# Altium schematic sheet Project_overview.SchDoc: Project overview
size A4; Date: Not used; ApprovedBy: Not used; CheckedBy: Not used; Author: Not used; CompanyName: STMicroelectronics; DrawnBy: Not used; Engineer: Not used; Organization: Not used; Address1: Not used; Address2: Not used; Address3: Not used; Address4: Not used; DocumentNumber: 1; Revision: Not used; SheetNumber: 1; SheetTotal: 9
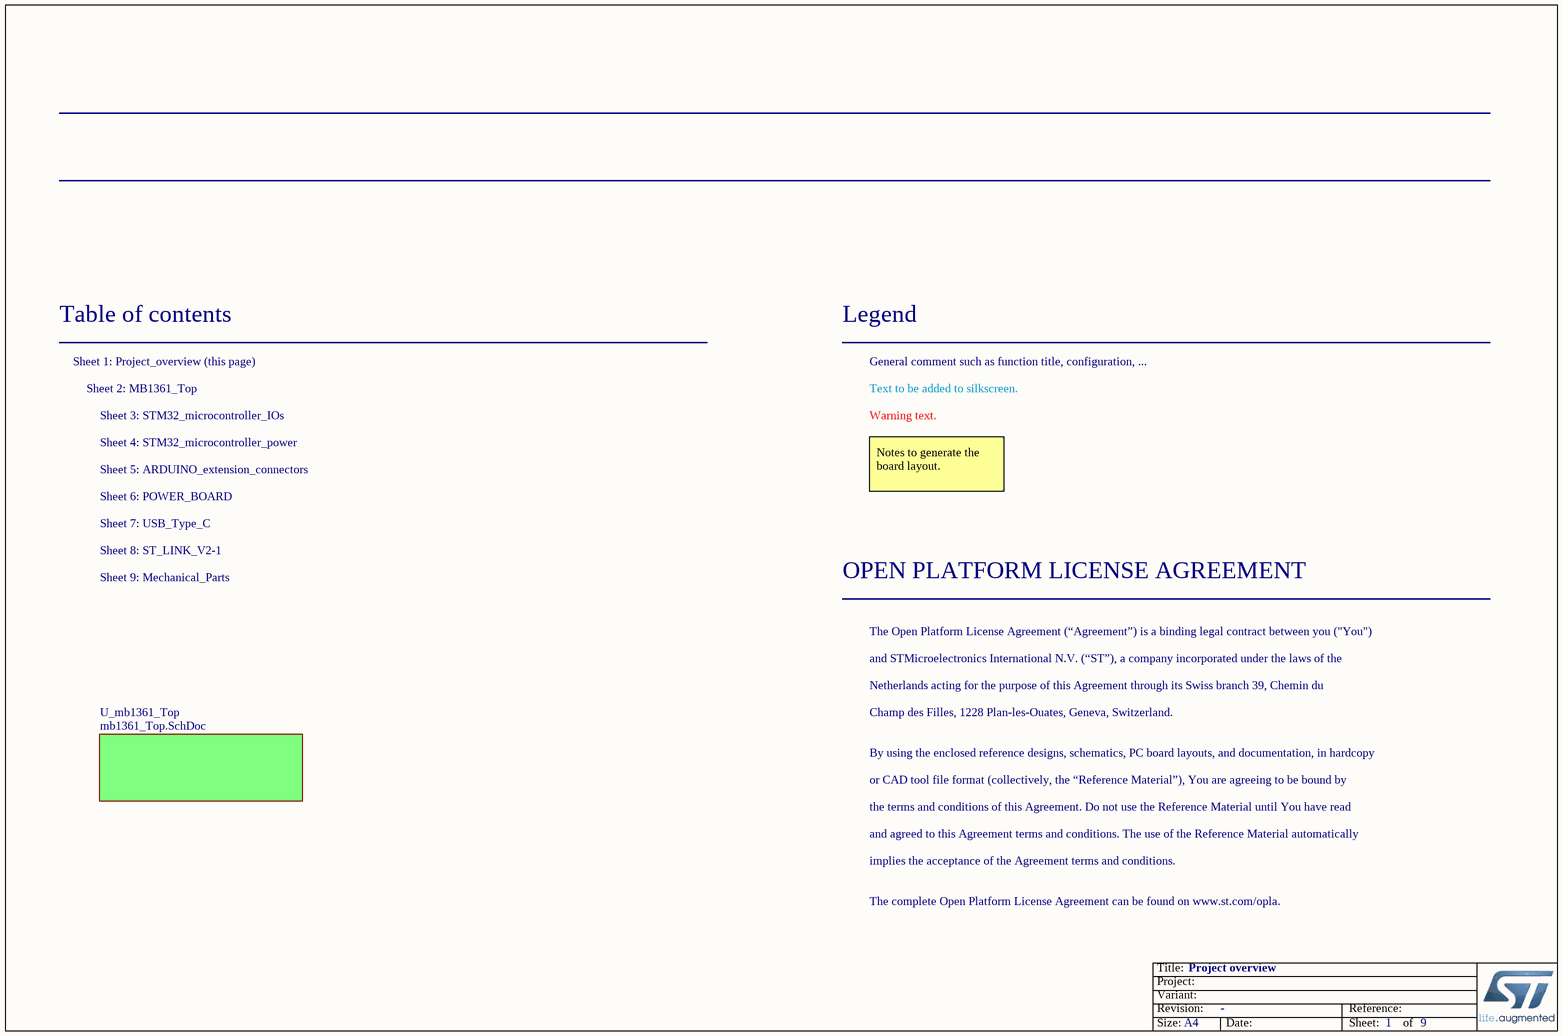
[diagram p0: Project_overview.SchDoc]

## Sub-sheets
U_mb1361_Top = mb1361_Top.SchDoc: no entries

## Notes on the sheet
- Table of contents
- Sheet 1: Project_overview (this page)
- Legend
- General comment such as function title, configuration, ...
- Sheet 2: MB1361_Top
- Sheet 4: STM32_microcontroller_power
- Sheet 3: STM32_microcontroller_IOs
- Text to be added to silkscreen.
- Warning text.
- Sheet 6: POWER_BOARD
- Sheet 5: ARDUINO_extension_connectors
- Notes to generate the board layout.
- Sheet 8: ST_LINK_V2-1
- Sheet 7: USB_Type_C
- Sheet 9: Mechanical_Parts
- OPEN PLATFORM LICENSE AGREEMENT
- The Open Platform License Agreement (“Agreement”) is a binding legal contract between you ("You")
- and STMicroelectronics International N.V. (“ST”), a company incorporated under the laws of the
- Netherlands acting for the purpose of this Agreement through its Swiss branch 39, Chemin du
- Champ des Filles, 1228 Plan-les-Ouates, Geneva, Switzerland.
- By using the enclosed reference designs, schematics, PC board layouts, and documentation, in hardcopy
- or CAD tool file format (collectively, the “Reference Material”), You are agreeing to be bound by
- the terms and conditions of this Agreement. Do not use the Reference Material until You have read
- and agreed to this Agreement terms and conditions. The use of the Reference Material automatically
- implies the acceptance of the Agreement terms and conditions.
- The complete Open Platform License Agreement can be found on www.st.com/opla.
